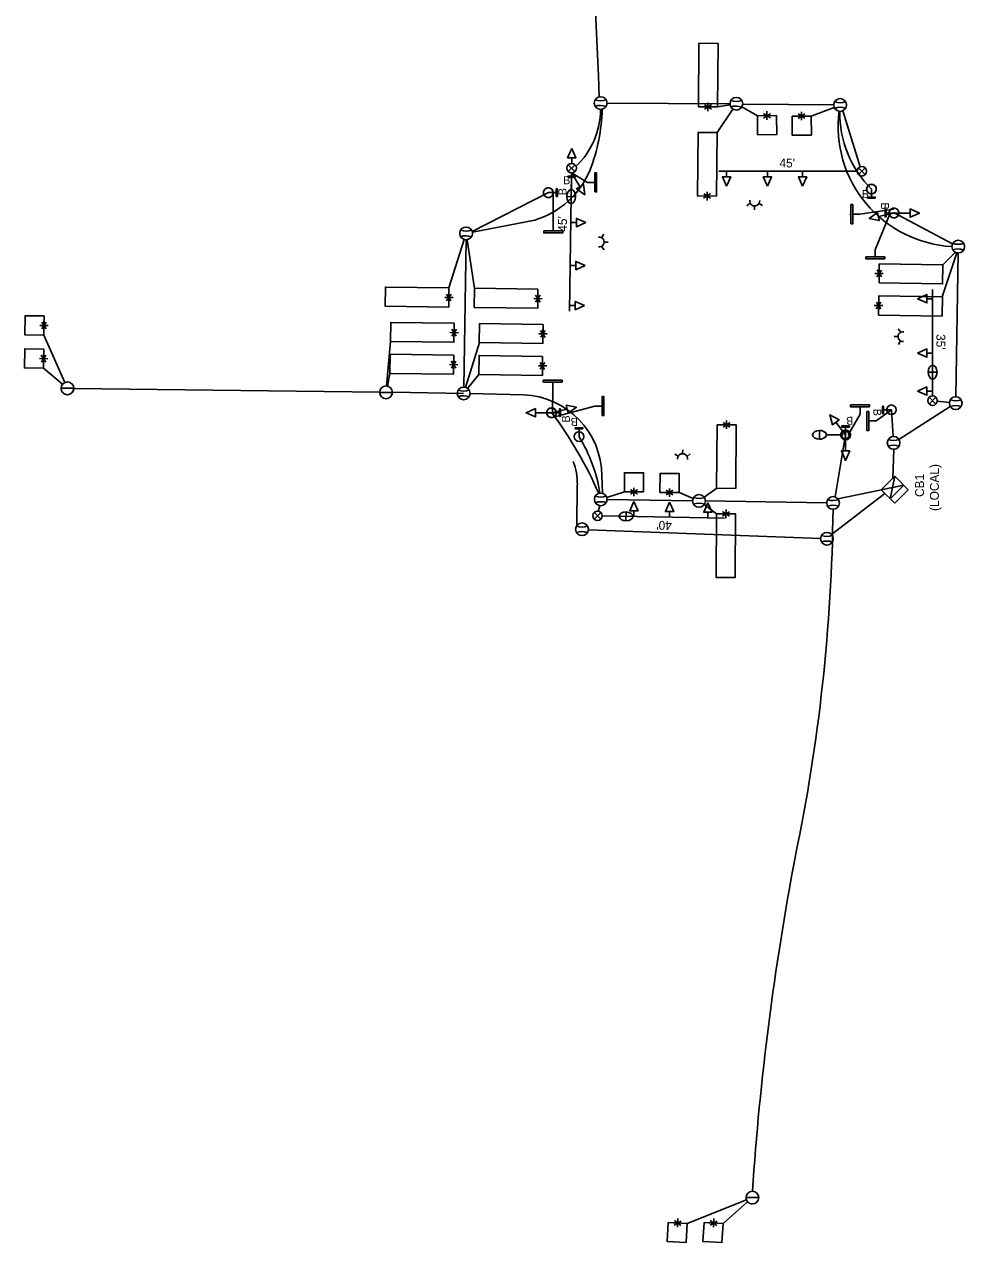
# Model space of a CAD drawing. Extents: x 596176 to 605330, y 332416 to 402398.
# Drawn here: x 604842.3 to 605137.8, y 332415.7 to 332799.2 of the extents above; entities that cross this region are included whole.
import ezdxf

# ---------------------------------------------------------------- set-up
doc = ezdxf.new("R2010")
doc.units = 0
for name, color, linetype in [('P_LTG', 7, 'Continuous'), ('P_SIG', 7, 'Continuous'), ('P_SIG_Bold', 7, 'Continuous'), ('P_SIG_Conduit', 7, 'Continuous'), ('P_SIG_IC', 7, 'Continuous'), ('P_SIG_Loops', 7, 'Continuous'), ('P_SIG_SignalHeads', 7, 'Continuous'), ('P_SIG_Text', 7, 'Continuous')]:
    doc.layers.add(name, color=color, linetype=linetype)

# ---------------------------------------------------------------- blocks, each defined once
blk = doc.blocks.new('CONTROL CABINET')
at = {"layer": 'P_SIG'}
for p, q in [((-0.229, 0.305), (0.229, 0.305)), ((-0.229, -0.152), (-0.229, 0.305)), ((0.229, 0.305), (0.229, -0.152)), ((-0.229, 0.152), (0.229, 0.152)), ((-0.229, -0.152), (0.229, 0.152)), ((0.229, -0.152), (-0.229, 0.152)), ((0.229, -0.152), (-0.229, -0.152))]:
    blk.add_line(p, q, dxfattribs=at)
blk = doc.blocks.new('BASE - PEDESTRIAN')
at = {"layer": 'P_SIG'}
blk.add_circle((0, 0.1), 4.57, dxfattribs=at)
blk = doc.blocks.new('_U329')
at = {"layer": 'P_SIG_Bold'}
for p, q in [((-3.429, 0), (-0.114, 0)), ((-0.081, 0.081), (0.081, -0.081)), ((0.081, 0.081), (-0.081, -0.081))]:
    blk.add_line(p, q, dxfattribs=at)
blk.add_circle((0, 0), 0.114, dxfattribs=at)
blk.add_text("45'", height=0.2134, dxfattribs=at).set_placement((-1.978, 0.092))
blk = doc.blocks.new('HEAD - TEMPORARY')
at = {"layer": 'P_SIG'}
blk.add_line((5.4, 0), (0, 0), dxfattribs=at)
blk.add_lwpolyline([(14.4, 0), (5.4, -4), (5.4, 4)], close=True, dxfattribs=at)
blk = doc.blocks.new('_U227')
at = {"layer": 'P_SIG'}
blk.add_circle((0, 0), 6.1, dxfattribs=at)
for centre, start, end in [((-15.5, 0.1), 336.6741, 22.5272), ((15.5, 0.1), 157.5751, 203.4282)]:
    blk.add_arc(centre, 13.3, start, end, dxfattribs=at)
blk = doc.blocks.new('_U226')
at = {"layer": 'P_SIG'}
blk.add_line((0, 6.1), (0, -6.1), dxfattribs=at)
blk.add_lwpolyline([(0, -6.1), (0, 6.1)], dxfattribs=at)
blk.add_circle((0, 0), 6.1, dxfattribs=at)
for start, end in [(89.7008, 180), (180, 269.7008)]:
    blk.add_arc((0, 0), 6.1, start, end, dxfattribs=at)
blk = doc.blocks.new('_U306')
at = {"layer": 'P_SIG_Loops'}
for p, q in [((-0.055, -0.084), (0.052, 0.081)), ((0.056, -0.083), (-0.053, 0.082)), ((0, 0), (0, -0.229)), ((-0.105, -0.001), (0.099, -0.001))]:
    blk.add_line(p, q, dxfattribs=at)
blk.add_lwpolyline([(0, -0.229), (1.524, -0.229), (1.524, 0.229), (0, 0.229)], close=True, dxfattribs=at)
blk = doc.blocks.new('_U312')
at = {"layer": 'P_SIG_Loops'}
for p, q in [((-0.055, -0.084), (0.052, 0.081)), ((0.056, -0.083), (-0.053, 0.082)), ((0, 0), (0, -0.229)), ((-0.105, -0.001), (0.099, -0.001))]:
    blk.add_line(p, q, dxfattribs=at)
blk.add_lwpolyline([(0, -0.229), (0.457, -0.229), (0.457, 0.229), (0, 0.229)], close=True, dxfattribs=at)
blk = doc.blocks.new('_U334')
at = {"layer": 'P_SIG_Bold'}
for p, q in [((-2.667, 0), (-0.114, 0)), ((-0.081, 0.081), (0.081, -0.081)), ((0.081, 0.081), (-0.081, -0.081))]:
    blk.add_line(p, q, dxfattribs=at)
blk.add_circle((0, 0), 0.114, dxfattribs=at)
blk.add_text("35'", height=0.2134, dxfattribs=at).set_placement((-1.597, 0.092))
blk = doc.blocks.new('_U304')
at = {"layer": 'P_SIG_Bold'}
for p, q in [((-3.048, 0), (-0.114, 0)), ((-0.081, 0.081), (0.081, -0.081)), ((0.081, 0.081), (-0.081, -0.081))]:
    blk.add_line(p, q, dxfattribs=at)
blk.add_circle((0, 0), 0.114, dxfattribs=at)
blk.add_text("40'", height=0.2134, dxfattribs=at).set_placement((-1.787, 0.092))
blk = doc.blocks.new('_U327')
at = {"layer": 'P_SIG_Bold'}
for p, q in [((-3.429, 0), (-0.114, 0)), ((-0.081, 0.081), (0.081, -0.081)), ((0.081, 0.081), (-0.081, -0.081))]:
    blk.add_line(p, q, dxfattribs=at)
blk.add_circle((0, 0), 0.114, dxfattribs=at)
blk.add_text("45'", height=0.2134, dxfattribs=at).set_placement((-1.528, 0.092))
blk = doc.blocks.new('CONFIRMATION LIGHT')
at = {"layer": 'P_SIG'}
for p, q in [((-4.2, 3), (-7.5, 4.8)), ((0, 5.5), (0, 9.2)), ((4.3, 2.9), (7.3, 5.5))]:
    blk.add_line(p, q, dxfattribs=at)
blk.add_arc((0, 0.6), 4.81, 352.2462, 187.7538, dxfattribs=at)
blk = doc.blocks.new('_U225')
at = {"layer": 'P_SIG'}
blk.add_circle((0, 0), 6.1, dxfattribs=at)
for centre, start, end in [((-15.5, 0.1), 336.6741, 22.5272), ((15.5, 0.1), 157.5751, 203.4282)]:
    blk.add_arc(centre, 13.3, start, end, dxfattribs=at)

msp = doc.modelspace()

# ---------------------------------------------------------------- linework, layer by layer
at = {"layer": 'P_LTG'}
for p, q in [((605014.67, 332752.47), (605014.59, 332747.18)), ((605013.15, 332745.01), (605015.93, 332744.96)), ((605129.73, 332689.77), (605126.96, 332689.77)), ((605128.33, 332682.28), (605128.33, 332687.58)), ((605092.7, 332671.4), (605092.7, 332668.63)), ((605100.19, 332670), (605094.89, 332670)), ((605024.32, 332644.5), (605029.62, 332644.4)), ((605031.78, 332642.95), (605031.84, 332645.73))]:
    msp.add_line(p, q, dxfattribs=at)
msp.add_circle((605100.89, 332670), 1.21, dxfattribs=at)
for centre, major_axis in [((605014.54, 332744.99), (-0.03, -2.18)), ((605128.34, 332689.77), (0, 2.18)), ((605092.7, 332670.02), (-2.18, 0)), ((605031.81, 332644.34), (2.18, -0.04))]:
    msp.add_ellipse(centre, major_axis=major_axis, ratio=0.636439, dxfattribs=at)
for centre, major_axis in [((605014.54, 332744.99), (-0.03, -2.18)), ((605128.34, 332689.77), (0, 2.18)), ((605092.7, 332670.02), (-2.18, 0)), ((605031.81, 332644.34), (2.18, -0.04))]:
    msp.add_ellipse(centre, major_axis=major_axis, ratio=0.636439, start_param=1.570796, end_param=4.712389, dxfattribs=at)
at = {"layer": 'P_SIG'}
for p, q in [((605019.67, 332749.43), (605014.67, 332752.47)), ((605017.29, 332748.14), (605014.67, 332752.47)), ((605007.35, 332746.25), (605009.85, 332746.25)), ((605008.85, 332736.46), (605008.9, 332746.25)), ((605019.67, 332749.43), (605022.07, 332749.43)), ((605109.09, 332747.36), (605109.09, 332744.86)), ((605102.26, 332739.29), (605102.6, 332739.48)), ((605105.46, 332739.52), (605103.06, 332739.52)), ((605105.46, 332739.52), (605116.1, 332741.08)), ((605110.24, 332728.3), (605114.94, 332739.84)), ((605111.26, 332738.74), (605116.19, 332739.84)), ((605116.19, 332739.84), (605113.69, 332739.84)), ((605121.25, 332739.82), (605116.19, 332739.84)), ((605008.85, 332736.46), (605008.85, 332734.06)), ((605110.24, 332728.3), (605110.24, 332725.9)), ((605008.78, 332684.35), (605008.7, 332677.17)), ((605008.78, 332684.35), (605008.78, 332686.75)), ((605003.28, 332676.98), (605008.34, 332676.97)), ((605013.27, 332678.07), (605008.34, 332676.96)), ((605008.34, 332676.97), (605010.84, 332676.97)), ((605021.98, 332679.03), (605008.5, 332675.46)), ((605021.98, 332679.03), (605024.38, 332679.03)), ((605105.55, 332676.54), (605105.55, 332678.94)), ((605110.53, 332674.38), (605115.37, 332677.88)), ((605115.37, 332677.88), (605112.87, 332677.88)), ((605097.84, 332673.98), (605100.94, 332669.99)), ((605105.55, 332676.54), (605101.79, 332669.99)), ((605110.53, 332674.38), (605108.13, 332674.38)), ((605017, 332669.42), (605017, 332671.92)), ((605100.93, 332664.93), (605100.94, 332669.99)), ((605100.94, 332669.99), (605100.94, 332672.49))]:
    msp.add_line(p, q, dxfattribs=at)
for points in [[(605013.47, 332751.47), (605015.87, 332751.47), (605015.87, 332751.15), (605013.47, 332751.15)], [(605021.93, 332746.47), (605021.93, 332752.47), (605022.53, 332752.47), (605022.53, 332746.47)], [(605009.85, 332745.05), (605009.85, 332747.45), (605010.18, 332747.45), (605010.18, 332745.05)], [(605103.2, 332742.48), (605103.2, 332736.48), (605102.6, 332736.48), (605102.6, 332742.48)], [(605107.89, 332744.86), (605110.29, 332744.86), (605110.29, 332744.53), (605107.89, 332744.53)], [(605113.69, 332741.04), (605113.69, 332738.64), (605113.36, 332738.64), (605113.36, 332741.04)], [(605005.9, 332734.2), (605011.9, 332734.2), (605011.9, 332733.6), (605005.9, 332733.6)], [(605107.28, 332726.03), (605113.28, 332726.04), (605113.28, 332725.43), (605107.28, 332725.43)], [(605011.73, 332686.62), (605005.73, 332686.61), (605005.73, 332687.22), (605011.73, 332687.22)], [(605024.25, 332676.07), (605024.25, 332682.07), (605024.85, 332682.07), (605024.85, 332676.07)], [(605010.84, 332675.77), (605010.84, 332678.17), (605011.16, 332678.17), (605011.16, 332675.77)], [(605108.5, 332678.81), (605102.5, 332678.81), (605102.5, 332679.41), (605108.51, 332679.41)], [(605108.27, 332677.34), (605108.27, 332671.34), (605107.67, 332671.34), (605107.67, 332677.34)], [(605112.89, 332679.08), (605112.89, 332676.68), (605112.57, 332676.68), (605112.57, 332679.08)], [(605018.2, 332671.92), (605015.8, 332671.92), (605015.8, 332672.25), (605018.2, 332672.25)], [(605102.14, 332672.48), (605099.74, 332672.48), (605099.74, 332672.81), (605102.14, 332672.81)]]:
    msp.add_lwpolyline(points, close=True, dxfattribs=at)
for points in [[(605018.82, 332745.61), (605016.16, 332747.46), (605018.41, 332748.83), (605018.82, 332745.61)], [(605018.82, 332745.61), (605016.16, 332747.46), (605018.41, 332748.83), (605018.82, 332745.61)], [(605016.16, 332747.46), (605018.82, 332745.61), (605018.41, 332748.83), (605016.16, 332747.46)], [(605108.37, 332738.08), (605110.96, 332740.02), (605111.55, 332737.45), (605108.37, 332738.08)], [(605110.96, 332740.02), (605108.37, 332738.08), (605111.55, 332737.45), (605110.96, 332740.02)], [(605124.21, 332739.82), (605121.25, 332738.51), (605121.25, 332741.14), (605124.21, 332739.82)], [(605121.25, 332738.51), (605124.21, 332739.82), (605121.25, 332741.14), (605121.25, 332738.51)], [(605000.32, 332676.98), (605003.28, 332678.3), (605003.28, 332675.66), (605000.32, 332676.98)], [(605003.28, 332678.3), (605000.32, 332676.98), (605003.28, 332675.66), (605003.28, 332678.3)], [(605016.16, 332678.72), (605013.56, 332676.79), (605012.98, 332679.35), (605016.16, 332678.72)], [(605013.56, 332676.79), (605016.16, 332678.72), (605012.98, 332679.35), (605013.56, 332676.79)], [(605096.02, 332676.32), (605098.88, 332674.79), (605096.8, 332673.17), (605096.02, 332676.32)], [(605098.88, 332674.79), (605096.02, 332676.32), (605096.8, 332673.17), (605098.88, 332674.79)], [(605100.93, 332661.97), (605099.61, 332664.93), (605102.25, 332664.93), (605100.93, 332661.97)], [(605099.61, 332664.93), (605100.93, 332661.97), (605102.25, 332664.93), (605099.61, 332664.93)]]:
    msp.add_lwpolyline(points, dxfattribs=at)
for centre in [(605007.32, 332746.24), (605109.08, 332747.37), (605116.19, 332739.84), (605116.19, 332739.84), (605116.19, 332739.84), (605116.19, 332739.84), (605116.19, 332739.84), (605116.19, 332739.84), (605008.34, 332676.97), (605008.34, 332676.97), (605008.34, 332676.97), (605008.34, 332676.96), (605008.34, 332676.96), (605008.34, 332676.96), (605100.94, 332669.99), (605100.94, 332669.99), (605100.94, 332669.99), (605100.94, 332669.99), (605100.94, 332669.99), (605100.94, 332669.99)]:
    msp.add_circle(centre, 1.52, dxfattribs=at)
for centre, start, end in [((605007.32, 332746.24), 12.7754, 192.7754), ((605007.32, 332746.24), 192.7754, 12.7754), ((605109.08, 332747.37), 12.7754, 192.7754), ((605109.08, 332747.37), 192.7754, 12.7754), ((605116.19, 332739.84), 12.7754, 192.7754), ((605116.19, 332739.84), 0, 180), ((605116.19, 332739.84), 180, 0), ((605116.19, 332739.84), 192.7754, 12.7754), ((605008.34, 332676.97), 0, 180), ((605008.34, 332676.96), 12.7754, 192.7754), ((605008.34, 332676.97), 180, 0), ((605008.34, 332676.96), 192.7754, 12.7754), ((605100.94, 332669.99), 90, 270), ((605100.94, 332669.99), 127.9106, 307.9106), ((605100.94, 332669.99), 307.9106, 127.9106), ((605100.94, 332669.99), 270, 90)]:
    msp.add_arc(centre, 1.52, start, end, dxfattribs=at)
at = {"layer": 'P_SIG_Conduit'}
for p, q in [((605100.08, 332772.04), (605105.52, 332754.37)), ((604857.91, 332684.65), (604954.25, 332683.48))]:
    msp.add_line(p, q, dxfattribs=at)
for points in [[(605025.8, 332774.43), (605064.64, 332774.17)], [(605068.64, 332774.14), (605097.22, 332773.87)], [(604983.34, 332734.06), (605007.35, 332746.25)], [(605134.62, 332730.15), (605115.99, 332739.99)], [(604983.41, 332733.8), (605003.04, 332737.58)], [(604980.7, 332685.05), (604981.48, 332731.41)], [(605136.38, 332727.27), (605135.67, 332681.99)], [(604980.66, 332683.05), (604958.25, 332683.4)], [(604999.49, 332682.65), (604982.66, 332683.06)], [(605133.65, 332680.2), (605129.82, 332680.62)], [(605115.91, 332669.49), (605115.37, 332677.88)], [(605117.72, 332668.57), (605133.92, 332678.96)], [(605097.64, 332650.48), (605100.94, 332669.99)], [(605115.82, 332656.32), (605116.1, 332665.49)], [(605024.35, 332651.63), (605024.23, 332657.08)], [(605098.49, 332649.92), (605112.22, 332652.71)], [(605023.55, 332647.71), (605023.08, 332646.02)], [(605052.78, 332649.26), (605025.86, 332649.66)], [(605095, 332648.62), (605056.77, 332649.2)]]:
    msp.add_lwpolyline(points, dxfattribs=at)
for centre, radius, start, end in [((600031.92, 332578.64), 4995.36, 2.26878, 4.72053), ((604998.97, 332772.55), 24.8, 313.501, 359.733), ((604966.45, 332774.16), 57.88, 339.0115, 358.3523), ((605136.43, 332767.07), 37.83, 172.7012, 266.9456), ((605132.81, 332771.29), 33.69, 179.0451, 225.2562), ((604995.05, 332763.89), 27.49, 286.8873, 337.6501), ((604998.4, 332656.85), 25.83, 0.5144, 87.5848), ((604908.2, 332601.7), 125.34, 23.4466, 36.9043), ((604976.23, 332644.18), 47.95, 8.9921, 31.7677), ((604529.61, 332652.95), 567.41, 348.2085, 359.3579), ((605948.01, 332373.18), 878.37, 169.25156, 176.16781)]:
    msp.add_arc(centre, radius, start, end, dxfattribs=at)
at = {"layer": 'P_SIG_IC'}
msp.add_line((605019.94, 332640.16), (605093.06, 332637.39), dxfattribs=at)
for points in [[(605016.29, 332641.42), (605016.46, 332654.32)], [(605096.54, 332638.66), (605113.33, 332651.58)]]:
    msp.add_lwpolyline(points, dxfattribs=at)
msp.add_arc((604996.47, 332654.58), 20, 359.2508, 20.6671, dxfattribs=at)
at = {"layer": 'P_SIG_Loops'}
for p, q in [((605065.44, 332772.57), (605060.5, 332765.18)), ((605064.58, 332773.9), (605060.58, 332773.22)), ((605068.29, 332773.24), (605073.18, 332770.46)), ((605090.08, 332770.36), (605097.39, 332773.06)), ((604976.04, 332716.24), (604980.85, 332731.5)), ((604984.09, 332716.13), (604981.76, 332731.43)), ((605131.4, 332713.42), (605135.96, 332727.32)), ((605135.54, 332727.47), (605131.56, 332723.5)), ((604855.1, 332686.49), (604848.47, 332701.42)), ((604957.61, 332699.42), (604956.42, 332685.38)), ((604981.27, 332684.96), (604985.61, 332699.04)), ((604848.34, 332690.99), (604854.38, 332685.94)), ((604956.64, 332685.35), (604957.46, 332689.37)), ((604985.45, 332688.99), (604981.92, 332684.61)), ((605031.29, 332652.1), (605025.76, 332650.3)), ((605052.93, 332650), (605048.49, 332651.86)), ((605060.35, 332653.18), (605056.41, 332650.38)), ((605056.38, 332648.04), (605060.31, 332645.14)), ((605069.73, 332429.15), (605051.07, 332421.73)), ((605062.38, 332421.71), (605070.05, 332428.61))]:
    msp.add_line(p, q, dxfattribs=at)

# ---------------------------------------------------------------- block references
at = {"layer": 'P_SIG'}
for name, p, xscale, yscale, rotation in [('HEAD - TEMPORARY', (605014.7, 332755.47), 0.32808333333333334, 0.32808333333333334, 89.13535792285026), ('_U327', (605014.67, 332753.97), 13.123333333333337, 13.123333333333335, 89.13535792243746), ('HEAD - TEMPORARY', (605063.46, 332752.98), 0.32808333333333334, 0.32808333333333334, -90.00000000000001), ('HEAD - TEMPORARY', (605076.35, 332752.98), 0.32808333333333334, 0.32808333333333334, -90.00000000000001), ('HEAD - TEMPORARY', (605087.39, 332752.98), 0.32808333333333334, 0.32808333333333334, -90.00000000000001), ('_U334', (605128.33, 332680.78), 13.123333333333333, 13.123333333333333, -90.00000000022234), ('HEAD - TEMPORARY', (605128.31, 332712.88), 0.32808333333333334, 0.32808333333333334, 180), ('HEAD - TEMPORARY', (605128.31, 332695.75), 0.32808333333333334, 0.32808333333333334, 180), ('HEAD - TEMPORARY', (605128.31, 332683.78), 0.32808333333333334, 0.32808333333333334, 180), ('CONTROL CABINET', (605115.73, 332653.43), 13.123333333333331, 13.12333333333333, -135.37543928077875), ('CONTROL CABINET', (605115.73, 332653.43), 13.123333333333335, 13.123333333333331, -135.29557835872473), ('_U304', (605022.83, 332644.54), 13.123333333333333, 13.12333333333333, 178.87701025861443), ('HEAD - TEMPORARY', (605034.31, 332644.32), 0.32808333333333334, 0.32808333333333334, 90), ('HEAD - TEMPORARY', (605045.51, 332644.1), 0.32808333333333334, 0.32808333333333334, 90), ('HEAD - TEMPORARY', (605057.59, 332643.86), 0.32808333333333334, 0.32808333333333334, 90)]:
    msp.add_blockref(name, p, dxfattribs=dict(at, xscale=xscale, yscale=yscale, rotation=rotation))
at = {"layer": 'P_SIG', "xscale": 0.32808333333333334, "yscale": 0.32808333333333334}
for name, p in [('HEAD - TEMPORARY', (605014.41, 332736.84)), ('HEAD - TEMPORARY', (605014.21, 332723.32)), ('HEAD - TEMPORARY', (605014.02, 332710.72)), ('BASE - PEDESTRIAN', (605115.37, 332677.88)), ('BASE - PEDESTRIAN', (605017, 332669.42))]:
    msp.add_blockref(name, p, dxfattribs=at)
at = {"layer": 'P_SIG_Bold', "xscale": 13.123333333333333, "yscale": 13.123333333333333}
msp.add_blockref('_U329', (605106.07, 332752.98), dxfattribs=at)
at = {"layer": 'P_SIG_Conduit', "xscale": 0.32808333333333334, "yscale": 0.32808333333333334, "rotation": 90}
for name, p in [('_U227', (605023.81, 332774.44)), ('_U227', (605066.56, 332774.23)), ('_U227', (605099.23, 332773.85)), ('_U227', (604981.46, 332733.41)), ('_U227', (605136.42, 332729.27)), ('_U226', (604855.92, 332684.66)), ('_U226', (604956.25, 332683.39)), ('_U227', (604980.67, 332683.05)), ('_U227', (605135.64, 332679.99)), ('_U227', (605116.04, 332667.49)), ('_U227', (605023.86, 332649.69)), ('_U227', (605054.78, 332649.23)), ('_U227', (605097.01, 332648.59)), ('_U226', (605071.59, 332429.89))]:
    msp.add_blockref(name, p, dxfattribs=at)
at = {"layer": 'P_SIG_IC', "xscale": 0.32808333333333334, "yscale": 0.32808333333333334, "rotation": 90}
for p in [(605017.94, 332640.28), (605095.06, 332637.31)]:
    msp.add_blockref('_U225', p, dxfattribs=at)
at = {"layer": 'P_SIG_Loops'}
for name, p, xscale, yscale, rotation in [('_U306', (605057.58, 332773.25), 13.123333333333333, 13.123333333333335, 89.45794576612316), ('_U312', (605076.18, 332770.49), 13.123333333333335, 13.123333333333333, -89.31932784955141), ('_U312', (605087.08, 332770.33), 13.123333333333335, 13.123333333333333, -89.31932784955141), ('_U306', (605057.31, 332745.21), 13.123333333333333, 13.123333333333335, 89.45794576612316), ('_U306', (605111.51, 332720.82), 13.123333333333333, 13.123333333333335, -0.8970914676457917), ('_U306', (604976, 332713.24), 13.123333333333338, 13.123333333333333, 179.2211160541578), ('_U306', (605004.04, 332712.86), 13.123333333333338, 13.123333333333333, 179.2211160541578), ('_U306', (605111.36, 332710.73), 13.123333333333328, 13.12333333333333, -0.8970832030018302), ('_U312', (604848.51, 332704.42), 13.123333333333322, 13.123333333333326, 179.17384230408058), ('_U306', (604977.65, 332702.15), 13.123333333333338, 13.123333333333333, 179.2211160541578), ('_U306', (605005.64, 332701.77), 13.123333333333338, 13.123333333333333, 179.2211160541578), ('_U312', (604848.39, 332693.99), 13.123333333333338, 13.123333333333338, 178.99878615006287), ('_U306', (604977.5, 332692.1), 13.123333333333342, 13.123333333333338, 179.2211160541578), ('_U306', (605005.49, 332691.72), 13.123333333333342, 13.123333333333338, 179.2211160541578), ('_U306', (605063.48, 332673.16), 13.123333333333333, 13.123333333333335, -90.3829651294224), ('_U312', (605034.29, 332652.08), 13.123333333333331, 13.123333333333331, 89.76700985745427), ('_U312', (605045.49, 332651.87), 13.123333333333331, 13.123333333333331, 89.76700985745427), ('_U306', (605063.29, 332645.12), 13.123333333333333, 13.123333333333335, -90.3829651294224), ('_U312', (605048.08, 332421.9), 13.123333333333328, 13.123333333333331, -93.30067811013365), ('_U312', (605059.39, 332421.9), 13.12333333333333, 13.12333333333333, -93.62438316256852)]:
    msp.add_blockref(name, p, dxfattribs=dict(at, xscale=xscale, yscale=yscale, rotation=rotation))
at = {"layer": 'P_SIG_SignalHeads'}
for p, xscale, yscale, rotation in [((605072.33, 332743.85), 0.32808333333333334, 0.3280833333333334, 178.2707158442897), ((605023.13, 332730.72), 0.32808333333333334, 0.32808333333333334, -90.86464207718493), ((605119.22, 332700.92), 0.32808333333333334, 0.32808333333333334, 89.13535792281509), ((605049.58, 332662.31), 0.3280833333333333, 0.32808333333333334, -1.7292841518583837)]:
    msp.add_blockref('CONFIRMATION LIGHT', p, dxfattribs=dict(at, xscale=xscale, yscale=yscale, rotation=rotation))

# ---------------------------------------------------------------- texts
at = {"layer": 'P_SIG'}
for rotation, p in [(360, (605012, 332748.9)), (90, (605013.06, 332745.46)), (360, (605106.05, 332744.55)), (270, (605112.08, 332743.15)), (270, (605109.68, 332678.23)), (90, (605014.12, 332673.93)), (180, (605016.59, 332675.36)), (180, (605103.35, 332675.69))]:
    msp.add_text('B', height=2.52, rotation=rotation, dxfattribs=at).set_placement(p)
at = {"layer": 'P_SIG_Text'}
for s, p in [('CB1', (605125.64, 332650.46)), ('(LOCAL)', (605130.31, 332646.05))]:
    msp.add_text(s, height=2.8, rotation=90, dxfattribs=at).set_placement(p)

doc.saveas('drawing.dxf')
